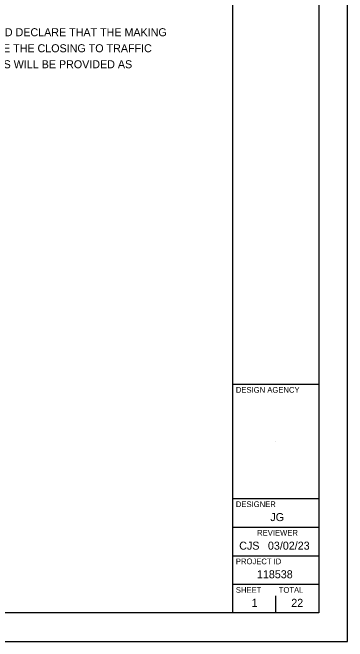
# Model space of a CAD drawing. Extents: x 0 to 81.5, y 0 to 35.2.
# Drawn here: x 28.15 to 34, y 0 to 11 of the extents above; entities that cross this region are included whole.
import ezdxf

# ---------------------------------------------------------------- set-up
doc = ezdxf.new("R2010")
doc.units = 0
for name, color, linetype in [('SH_Border', 7, 'Continuous'), ('SH_Cut_Line', 7, 'Continuous'), ('SH_Data', 7, 'Continuous'), ('SH_Text', 7, 'Continuous')]:
    doc.layers.add(name, color=color, linetype=linetype)

msp = doc.modelspace()

# ---------------------------------------------------------------- linework, layer by layer
at = {"layer": 'SH_Border'}
for p, q in [((32, 0.5), (32, 21.5)), ((32, 4.5), (33.5, 4.5)), ((32, 2.5), (33.5, 2.5)), ((32, 2), (33.5, 2)), ((32, 1.5), (33.5, 1.5)), ((32, 1), (33.5, 1))]:
    msp.add_line(p, q, dxfattribs=at)
msp.add_lwpolyline([(1.5, 21.5), (33.5, 21.5), (33.5, 0.5), (1.5, 0.5)], close=True, dxfattribs=at)
at = {"layer": 'SH_Cut_Line'}
msp.add_lwpolyline([(0, 0), (34, 0), (34, 22), (0, 22)], close=True, dxfattribs=at)
at = {"layer": 'SH_Data'}
for p, q in [((32.75, 3.5), (32.75, 3.5)), ((32.75, 0.5), (32.75, 0.8)), ((32.375, 0.675), (32.375, 0.675))]:
    msp.add_line(p, q, dxfattribs=at)

# ---------------------------------------------------------------- texts
for s, height, p in [('DESIGN AGENCY', 0.1, (32.05, 4.35)), ('DESIGNER', 0.1, (32.05, 2.35)), ('JG', 0.14, (32.653, 2.105)), ('REVIEWER', 0.1, (32.422, 1.85)), ('CJS', 0.14, (32.109, 1.605)), ('03/02/23', 0.14, (32.611, 1.605)), ('PROJECT ID', 0.1, (32.05, 1.35)), ('118538', 0.14, (32.419, 1.105)), ('SHEET', 0.1, (32.05, 0.85)), ('TOTAL', 0.1, (32.8, 0.85)), ('1', 0.14, (32.325, 0.605)), ('22', 0.14, (33.019, 0.605))]:
    msp.add_text(s, height=height, dxfattribs=at).set_placement(p)
at = {"layer": 'SH_Text'}
for s, p in [('I HEREBY APPROVE THESE PLANS AND DECLARE THAT THE MAKING ', (24.528, 10.586)), ('OF THIS IMPROVEMENT WILL REQUIRE THE CLOSING TO TRAFFIC ', (24.528, 10.306)), ('OF THE HIGHWAY AND THAT DETOURS WILL BE PROVIDED AS ', (24.528, 10.026))]:
    msp.add_text(s, height=0.14, dxfattribs=at).set_placement(p)

doc.saveas('drawing.dxf')
